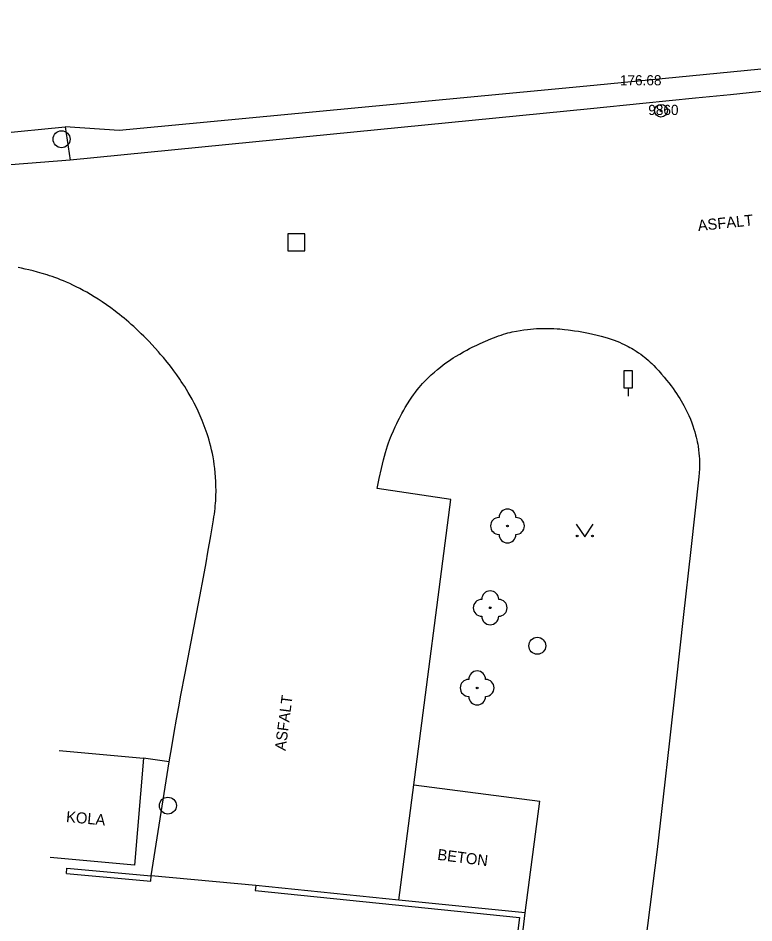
# Model space of a CAD drawing. Extents: x -541281 to -539153, y -1183881 to -1182141.
# Drawn here: x -540055.8 to -540012.4, y -1183251.3 to -1183197.9 of the extents above; entities that cross this region are included whole.
import ezdxf

# ---------------------------------------------------------------- set-up
doc = ezdxf.new("R2010")
doc.units = 0
for name, color, linetype in [('Vrstva 10', 7, 'Continuous'), ('Vrstva 11', 7, 'Continuous'), ('Vrstva 21', 7, 'Continuous'), ('Vrstva 22', 7, 'Continuous'), ('Vrstva 23', 7, 'Continuous'), ('Vrstva 26', 7, 'Continuous'), ('Vrstva 27', 7, 'Continuous'), ('Vrstva 36', 7, 'Continuous'), ('Vrstva 38', 7, 'Continuous'), ('Vrstva 40', 7, 'Continuous'), ('Vrstva 7', 7, 'Continuous'), ('Vrstva 8', 7, 'Continuous')]:
    doc.layers.add(name, color=color, linetype=linetype)

msp = doc.modelspace()

# ---------------------------------------------------------------- linework, layer by layer
at = {"layer": 'Vrstva 10'}
for p, q in [((-540022.01, -1183203.3), (-540037.36, -1183204.81)), ((-540030.25, -1183226.35), (-540034.59, -1183225.71)), ((-540032.432, -1183243.207), (-540030.25, -1183226.35)), ((-540044.691, -1183230.097), (-540044.576, -1183229.46)), ((-540016.524, -1183233.315), (-540016.945, -1183237.078)), ((-540033.311, -1183250), (-540032.432, -1183243.207)), ((-540017.72, -1183243.913), (-540018.075, -1183247.014)), ((-540018.075, -1183247.014), (-540018.93, -1183253.91))]:
    msp.add_line(p, q, dxfattribs=at)
for points in [[(-540007.303, -1183201.78), (-540010.979, -1183202.17), (-540013.736, -1183202.46), (-540015.804, -1183202.674)], [(-540015.804, -1183202.674), (-540018.907, -1183202.991), (-540022.01, -1183203.3)], [(-540037.36, -1183204.81), (-540052.71, -1183206.32), (-540060.49, -1183206.94)], [(-540053.766, -1183213.201), (-540053.921, -1183213.148), (-540054.072, -1183213.098), (-540054.364, -1183213.007), (-540054.639, -1183212.928), (-540054.898, -1183212.86), (-540055.142, -1183212.802), (-540055.371, -1183212.751), (-540055.586, -1183212.707), (-540055.789, -1183212.67)], [(-540046.244, -1183219.251), (-540046.424, -1183218.993), (-540046.589, -1183218.767), (-540046.737, -1183218.57), (-540046.871, -1183218.397), (-540046.99, -1183218.247), (-540047.206, -1183217.984), (-540047.373, -1183217.788), (-540047.501, -1183217.64), (-540047.698, -1183217.42), (-540047.9, -1183217.2), (-540048.058, -1183217.033), (-540048.213, -1183216.872), (-540048.367, -1183216.717), (-540048.518, -1183216.568), (-540048.668, -1183216.423), (-540048.816, -1183216.284), (-540048.961, -1183216.149), (-540049.105, -1183216.02), (-540049.247, -1183215.894), (-540049.387, -1183215.774), (-540049.526, -1183215.657), (-540049.662, -1183215.545), (-540049.796, -1183215.436), (-540049.929, -1183215.331), (-540050.06, -1183215.23), (-540050.319, -1183215.037), (-540050.571, -1183214.857), (-540050.816, -1183214.689), (-540051.054, -1183214.533), (-540051.285, -1183214.388), (-540051.511, -1183214.253), (-540051.73, -1183214.127), (-540051.942, -1183214.01), (-540052.149, -1183213.901), (-540052.35, -1183213.799), (-540052.546, -1183213.705), (-540052.736, -1183213.616), (-540052.92, -1183213.534), (-540053.099, -1183213.458), (-540053.274, -1183213.387), (-540053.443, -1183213.32), (-540053.607, -1183213.259), (-540053.766, -1183213.201)], [(-540029.501, -1183217.649), (-540029.306, -1183217.543), (-540029.134, -1183217.452), (-540028.981, -1183217.374), (-540028.712, -1183217.242), (-540028.507, -1183217.146), (-540028.195, -1183217.006), (-540027.88, -1183216.87), (-540027.724, -1183216.806), (-540027.572, -1183216.748), (-540027.423, -1183216.696), (-540027.279, -1183216.648), (-540027.139, -1183216.604), (-540027.002, -1183216.564), (-540026.87, -1183216.528), (-540026.741, -1183216.495), (-540026.615, -1183216.466), (-540026.372, -1183216.415), (-540026.143, -1183216.373), (-540025.927, -1183216.34), (-540025.725, -1183216.314), (-540025.534, -1183216.294), (-540025.356, -1183216.279), (-540025.189, -1183216.268), (-540025.032, -1183216.261), (-540024.884, -1183216.256), (-540024.609, -1183216.253), (-540024.368, -1183216.257), (-540024.158, -1183216.264), (-540023.975, -1183216.275), (-540023.815, -1183216.286), (-540023.536, -1183216.312), (-540023.327, -1183216.336), (-540023.172, -1183216.357), (-540022.94, -1183216.391), (-540022.71, -1183216.43), (-540022.404, -1183216.486), (-540022.119, -1183216.542), (-540021.854, -1183216.598), (-540021.607, -1183216.656), (-540021.377, -1183216.714), (-540021.162, -1183216.773), (-540020.963, -1183216.833), (-540020.776, -1183216.894), (-540020.603, -1183216.955), (-540020.441, -1183217.017), (-540020.29, -1183217.078), (-540020.15, -1183217.139), (-540020.019, -1183217.199)], [(-540020.019, -1183217.199), (-540019.896, -1183217.259), (-540019.782, -1183217.318)], [(-540034.59, -1183225.71), (-540034.466, -1183225.122), (-540034.342, -1183224.534), (-540034.283, -1183224.267), (-540034.222, -1183224.02), (-540034.161, -1183223.79), (-540034.099, -1183223.576), (-540034.038, -1183223.376), (-540033.977, -1183223.19), (-540033.917, -1183223.017), (-540033.858, -1183222.855), (-540033.801, -1183222.704), (-540033.745, -1183222.563), (-540033.635, -1183222.3), (-540033.533, -1183222.071), (-540033.439, -1183221.872), (-540033.354, -1183221.698), (-540033.276, -1183221.546), (-540033.134, -1183221.281), (-540033.023, -1183221.083), (-540032.936, -1183220.934), (-540032.801, -1183220.712), (-540032.66, -1183220.49), (-540032.55, -1183220.325), (-540032.44, -1183220.169), (-540032.331, -1183220.022), (-540032.223, -1183219.883), (-540032.116, -1183219.752), (-540032.01, -1183219.627), (-540031.906, -1183219.509), (-540031.803, -1183219.398), (-540031.701, -1183219.292), (-540031.601, -1183219.191), (-540031.503, -1183219.096), (-540031.406, -1183219.005), (-540031.216, -1183218.834), (-540031.033, -1183218.679), (-540030.857, -1183218.539), (-540030.69, -1183218.412), (-540030.53, -1183218.296), (-540030.379, -1183218.19), (-540030.234, -1183218.093), (-540030.097, -1183218.004), (-540029.968, -1183217.922), (-540029.721, -1183217.774), (-540029.501, -1183217.649)], [(-540019.782, -1183217.318), (-540019.676, -1183217.375), (-540019.576, -1183217.431), (-540019.483, -1183217.486), (-540019.31, -1183217.594), (-540019.16, -1183217.694)], [(-540019.16, -1183217.694), (-540019.029, -1183217.787), (-540018.916, -1183217.873), (-540018.817, -1183217.95), (-540018.731, -1183218.021), (-540018.581, -1183218.149), (-540018.47, -1183218.251), (-540018.387, -1183218.329), (-540018.263, -1183218.452), (-540018.14, -1183218.58), (-540017.966, -1183218.77), (-540017.803, -1183218.954), (-540017.65, -1183219.133), (-540017.507, -1183219.307), (-540017.373, -1183219.477), (-540017.248, -1183219.641), (-540017.131, -1183219.801), (-540017.021, -1183219.956), (-540016.919, -1183220.107), (-540016.823, -1183220.254), (-540016.734, -1183220.396), (-540016.65, -1183220.534), (-540016.572, -1183220.669), (-540016.499, -1183220.799), (-540016.431, -1183220.926), (-540016.367, -1183221.049), (-540016.308, -1183221.168), (-540016.253, -1183221.284), (-540016.201, -1183221.397), (-540016.107, -1183221.616), (-540016.025, -1183221.822), (-540015.955, -1183222.016), (-540015.894, -1183222.199), (-540015.842, -1183222.37), (-540015.797, -1183222.532), (-540015.758, -1183222.684), (-540015.725, -1183222.827), (-540015.697, -1183222.961), (-540015.673, -1183223.087), (-540015.653, -1183223.206), (-540015.621, -1183223.429), (-540015.6, -1183223.625), (-540015.585, -1183223.797), (-540015.576, -1183223.948), (-540015.571, -1183224.081), (-540015.569, -1183224.197), (-540015.57, -1183224.402), (-540015.575, -1183224.556), (-540015.589, -1183224.787), (-540015.61, -1183225.02)], [(-540045.847, -1183219.864), (-540045.952, -1183219.695), (-540046.053, -1183219.537), (-540046.15, -1183219.39), (-540046.244, -1183219.251)], [(-540044.576, -1183229.46), (-540044.41, -1183228.505), (-540044.25, -1183227.55), (-540044.224, -1183227.381), (-540044.2, -1183227.216), (-540044.18, -1183227.053), (-540044.162, -1183226.893), (-540044.147, -1183226.735), (-540044.134, -1183226.58), (-540044.123, -1183226.428), (-540044.115, -1183226.278), (-540044.109, -1183226.131), (-540044.103, -1183225.842), (-540044.105, -1183225.562), (-540044.113, -1183225.291), (-540044.128, -1183225.03), (-540044.149, -1183224.777), (-540044.175, -1183224.533), (-540044.205, -1183224.296), (-540044.24, -1183224.068), (-540044.279, -1183223.847), (-540044.32, -1183223.633), (-540044.365, -1183223.426), (-540044.413, -1183223.227), (-540044.463, -1183223.033), (-540044.515, -1183222.846), (-540044.568, -1183222.665), (-540044.623, -1183222.49), (-540044.68, -1183222.321), (-540044.737, -1183222.158), (-540044.795, -1183221.999), (-540044.854, -1183221.846), (-540044.914, -1183221.698), (-540044.973, -1183221.554), (-540045.033, -1183221.416), (-540045.155, -1183221.147), (-540045.276, -1183220.896), (-540045.395, -1183220.661), (-540045.513, -1183220.442), (-540045.627, -1183220.236), (-540045.739, -1183220.044), (-540045.847, -1183219.864)], [(-540015.61, -1183225.02), (-540016.079, -1183229.301), (-540016.524, -1183233.315)], [(-540046.433, -1183239.326), (-540046.3, -1183238.589), (-540046.172, -1183237.898), (-540045.929, -1183236.603), (-540045.059, -1183232.076), (-540044.846, -1183230.945), (-540044.691, -1183230.097)], [(-540016.945, -1183237.078), (-540017.343, -1183240.606), (-540017.72, -1183243.913)], [(-540047.93, -1183248.58), (-540047.395, -1183245.215), (-540046.86, -1183241.85), (-540046.714, -1183240.953), (-540046.571, -1183240.113), (-540046.433, -1183239.326)]]:
    msp.add_lwpolyline(points, dxfattribs=at)
at = {"layer": 'Vrstva 11'}
for p, q in [((-540053.01, -1183204.35), (-540052.71, -1183206.32)), ((-540046.86, -1183241.85), (-540048.38, -1183241.62)), ((-540032.432, -1183243.207), (-540024.99, -1183244.17)), ((-540025.85, -1183250.76), (-540024.99, -1183244.17))]:
    msp.add_line(p, q, dxfattribs=at)
at = {"layer": 'Vrstva 21'}
for radius in [0.375, 0.05]:
    msp.add_circle((-540017.84, -1183203.41), radius, dxfattribs=at)
at = {"layer": 'Vrstva 22'}
for centre in [(-540026.9, -1183227.92), (-540027.92, -1183232.75), (-540028.69, -1183237.48)]:
    msp.add_circle(centre, 0.05, dxfattribs=at)
for centre, start, end in [((-540026.9, -1183227.42), 0, 180), ((-540027.4, -1183227.92), 90, 270), ((-540026.4, -1183227.92), 270, 90), ((-540026.9, -1183228.42), 180, 0), ((-540027.92, -1183232.25), 0, 180), ((-540028.42, -1183232.75), 90, 270), ((-540027.42, -1183232.75), 270, 90), ((-540027.92, -1183233.25), 180, 0), ((-540028.69, -1183236.98), 0, 180), ((-540029.19, -1183237.48), 90, 270), ((-540028.19, -1183237.48), 270, 90), ((-540028.69, -1183237.98), 180, 0)]:
    msp.add_arc(centre, 0.5, start, end, dxfattribs=at)
at = {"layer": 'Vrstva 26'}
msp.add_lwpolyline([(-540039.86, -1183211.67), (-540038.86, -1183211.67), (-540038.86, -1183210.67), (-540039.86, -1183210.67)], close=True, dxfattribs=at)
at = {"layer": 'Vrstva 27'}
for centre in [(-540053.22, -1183205.09), (-540025.14, -1183234.99), (-540046.942, -1183244.428)]:
    msp.add_circle(centre, 0.5, dxfattribs=at)
at = {"layer": 'Vrstva 36'}
msp.add_lwpolyline([(-540022.837, -1183227.81), (-540022.337, -1183228.56), (-540021.837, -1183227.81)], dxfattribs=at)
for centre in [(-540022.787, -1183228.509), (-540021.888, -1183228.509)]:
    msp.add_circle(centre, 0.05, dxfattribs=at)
at = {"layer": 'Vrstva 38'}
msp.add_line((-540019.78, -1183219.765), (-540019.78, -1183220.25), dxfattribs=at)
msp.add_lwpolyline([(-540020.03, -1183219.765), (-540019.53, -1183219.765), (-540019.53, -1183218.765), (-540020.03, -1183218.765)], close=True, dxfattribs=at)
at = {"layer": 'Vrstva 7'}
for p, q in [((-539981.09, -1183197.94), (-540021.81, -1183201.92)), ((-540021.81, -1183201.92), (-540049.82, -1183204.57)), ((-540049.82, -1183204.57), (-540053.01, -1183204.35)), ((-540053.36, -1183241.168), (-540048.38, -1183241.62)), ((-540048.38, -1183241.62), (-540048.91, -1183247.94)), ((-540048.91, -1183247.94), (-540053.89, -1183247.488)), ((-540052.937, -1183248.426), (-540047.957, -1183248.878)), ((-540047.957, -1183248.878), (-540047.93, -1183248.58)), ((-540041.76, -1183249.14), (-540041.79, -1183249.438)), ((-540033.311, -1183250), (-540041.76, -1183249.14)), ((-540041.79, -1183249.438), (-540026.186, -1183251.027)), ((-540025.85, -1183250.76), (-540033.311, -1183250)), ((-540030.94, -1183290.74), (-540025.85, -1183250.76)), ((-540026.186, -1183251.027), (-540031.238, -1183290.702))]:
    msp.add_line(p, q, dxfattribs=at)
msp.add_lwpolyline([(-540052.937, -1183248.426), (-540052.91, -1183248.128), (-540047.93, -1183248.58)], dxfattribs=at)
at = {"layer": 'Vrstva 8'}
for p, q in [((-540060.35, -1183205.07), (-540053.01, -1183204.35)), ((-540041.76, -1183249.14), (-540047.93, -1183248.58))]:
    msp.add_line(p, q, dxfattribs=at)

# ---------------------------------------------------------------- texts
at = {"layer": 'Vrstva 22'}
msp.add_text('176.68', height=0.6, dxfattribs=at).set_placement((-540020.265, -1183201.91))
at = {"layer": 'Vrstva 23'}
msp.add_text('9860', height=0.6, dxfattribs=at).set_placement((-540018.59, -1183203.66))
at = {"layer": 'Vrstva 40'}
for s, rotation, p in [('ASFALT', 5.9689, (-540015.639, -1183210.515)), ('ASFALT', 82.6253, (-540039.999, -1183241.21)), ('KOLA', 354.8139, (-540052.972, -1183245.393)), ('BETON', 352.6269, (-540031.065, -1183247.622))]:
    msp.add_text(s, height=0.65, rotation=rotation, dxfattribs=at).set_placement(p)

doc.saveas('drawing.dxf')
